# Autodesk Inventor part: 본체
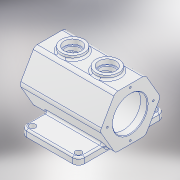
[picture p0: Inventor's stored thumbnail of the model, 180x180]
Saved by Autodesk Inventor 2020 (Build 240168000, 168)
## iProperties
Created: 2021-06
Part Number: 본체
Material: 알루미늄 6061
Document SubType Name: Modeling
Designer: MIRAE
Mass: 1495.28 g
Surface Area: 1102.36 cm^2
Volume: 553.806 cm^3
Density: 2.7 g/cm^3
Appearance: 알루미늄 - 평지
Author: MIRAE
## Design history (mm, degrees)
sketch "스케치1" dims "d0" = 105
  geometry: L1 (0, -52.5)-(-45.466, -26.25); L2 (-45.466, -26.25)-(-45.466, 26.25); L3 (-45.466, 26.25)-(0, 52.5); L4 (0, 52.5)-(45.466, 26.25); L5 (45.466, 26.25)-(45.466, -26.25); L6 (45.466, -26.25)-(0, -52.5); 3 further points
  constraints: 12 end point, 2 coincident, 1 vertical, 1 vertical alignment, 15 other
extrude "돌출1" new body sketch "스케치1" stored distance "d1" = 140; taper "d2" = 0 deg
sketch "스케치2"
  geometry: L1 (-70, 0)-(70, 0) reference; L2 (-70, 0)-(70, 0); L3 (-70, 0)-(-70, 30); L4 (-70, 45.466)-(-70, 0) reference; L5 (-70, 30)-(-58, 30); L6 (-58, 30)-(-58, 37.5); L7 (-58, 37.5)-(58, 37.5); L8 (58, 37.5)-(58, 30); L9 (58, 30)-(70, 30); L10 (70, 0)-(70, 45.466) reference; L11 (70, 30)-(70, 0); 1 further point
  constraints: 16 end point, 4 collinear, 4 perpendicular, 1 horizontal, 1 point on line
  dimensions: "d4" = 60 diameter of L5 L1; "d5" = 75 diameter of L7 L1; "d6" = 12 distance of L3.end L5.end
revolve "회전1" sketch "스케치2" stored, may be unused: angle "d7" = 90 deg
node "작업 평면1"
sketch "스케치3"
  geometry: L1 (35, -75)-(-45, -75); L2 (-55, -65)-(-55, 65); L3 (-45, 75)-(35, 75); L4 (45, 65)-(45, -65); L5 (70, -26.25)-(70, -52.5) reference; A1 r 10 centre (35, -65) between (35, -75) and (45, -65); A2 r 10 centre (-45, -65) between (-55, -65) and (-45, -75); A3 r 10 centre (-45, 65) between (-45, 75) and (-55, 65); A4 r 10 centre (35, 65) between (45, 65) and (35, 75); 4 further points
  constraints: 8 end point, 8 point on circle, 8 tangent, 6 point on line, 4 centre point, 3 equal radius, 2 parallel, 1 horizontal, 1 perpendicular
  dimensions: "d9" = 150 distance of point (-55, -75) point (-55, 75); "d10" = 25 distance between parallel lines of L4 L5; "d11" = 100 distance of point (45, -75) point (-55, -75); "d12" = 75 distance from line of point (0, 0) L1; "d13" = 10 radius of A1 (derived)
extrude "돌출2" join sketch "스케치3" distance "d14" = 12; taper "d15" = 0 deg
sketch "스케치4"
  geometry: C1 r 5.5 at (-35, 65); C2 r 5.5 at (45, 65); C3 r 5.5 at (45, -65); C4 r 5.5 at (-35, -65); A1 r 10 centre (-35, 65) between (-35, 75) and (-45, 65) reference; A2 r 10 centre (45, 65) between (55, 65) and (45, 75) reference; A3 r 10 centre (45, -65) between (45, -75) and (55, -65) reference; A4 r 10 centre (-35, -65) between (-45, -65) and (-35, -75) reference; 1 further point
  constraints: 4 centre point, 4 coincident
  dimensions: "d16" = 11 diameter of C1; "d17" = 11 diameter of C2; "d18" = 11 diameter of C3; "d19" = 11 diameter of C4
extrude "돌출3" cut sketch "스케치4" distance "d20" = 12; taper "d21" = 0 deg
node "작업 평면2"
sketch "스케치5"
  geometry: L1 (70, 26.25)-(70, -26.25) reference; C1 r 20 at (30, 0); C2 r 20 at (-30, 0); 1 further point
  constraints: 2 centre point, 2 horizontal alignment, 1 equal radius
  dimensions: "d23" = 40 distance from line of L1 C1.centre; "d24" = 60 distance of C2.centre C1.centre; "d25" = 40 diameter of C1
extrude "돌출4" join sketch "스케치5" stored distance "d26" = 12; taper "d27" = 0 deg
sketch "스케치6"
  geometry: C1 r 20 at (0, 0) reference; C2 r 20 at (60, 0) reference; 3 further points
  constraints: 2 coincident
hole "구멍1" sketch "스케치6" at (0, 0), (60, 0) diameter "d28" = 25; stored, may be unused: countersink angle "d32" = 90 deg, drill point angle "d34" = 118 deg; dims "d29" = 6, "d30" = 30, "d31" = 8, "d33" = 20
sketch "스케치7"
  geometry: L1 (0, 0)-(0, 40); L2 (0, 0)-(-28.284, 28.284); C1 r 40 at (0, 0); 2 further points
  constraints: 4 end point, 2 coincident, 1 centre point, 1 vertical
  dimensions: "d35" = 80 diameter of C1; "d36" = 45 deg angle of L1 L2; "d37" = 40 distance of L1.start L1.end; "d38" = 40 distance of point (0, 0) L2.end (= d37)
hole "구멍2" sketch "스케치7" at (-28.284, 28.284) diameter "d39" = 3.242; stored, may be unused: countersink angle "d43" = 90 deg, drill point angle "d45" = 118 deg; dims "d40" = 8, "d41" = 30, "d42" = 8, "d44" = 10
sketch "스케치8"
  geometry: C1 r 30 at (0, 0) reference; A1 r 40 centre (0, 0) between (0, 40) and (40, 0); 3 further points
  constraints: 4 point on circle, 2 horizontal alignment, 2 vertical alignment, 1 centre point, 1 coincident
  dimensions: "d49" = 80 diameter of A1
hole "구멍3" sketch "스케치8" at (0, 40), (40, 0), (0, -40), (-40, 0) diameter "d50" = 3.242; stored, may be unused: countersink angle "d54" = 90 deg, drill point angle "d56" = 118 deg; dims "d51" = 8, "d52" = 30, "d53" = 8, "d55" = 10
sketch "스케치9"
  geometry: L1 (45, 75)-(-35, 75) reference; L2 (-45, 65)-(-45, -65) reference; 2 further points
  constraints: 1 other
  dimensions: "d57" = 14 distance from line of point (5, 61) L1; "d58" = 50 distance from line of point (5, 61) L2
feature "엠보싱1" sketch "스케치9" dims "d0" = 105, "d4" = 60, "d5" = 75, "d6" = 12, "d59" = 0.5, "d60" = 0
fillet "모깎기1" dims "d61" = 5
fillet "모깎기2" dims "d62" = 8
fillet "모깎기3" dims "d63" = 3
fillet "모깎기4" dims "d64" = 3
fillet "모깎기5" dims "d65" = 3
chamfer "모따기1" distance "d66" = 1; stored, may be unused: second distance "d67" = 2, angle "d68" = 45 deg
chamfer "모따기2" distance "d69" = 1; stored, may be unused: second distance "d70" = 2, angle "d71" = 45 deg
node "솔리드1"
pattern_circular "원형 패턴1" dims angle "d47" = 360 deg
feature "A9D066F2-1C7D-4E18-AEED-F7BC21143FA4" dims "d39" = 3.242, "d40" = 8, "d41" = 30, "d42" = 8, "d43" = 90 deg, "d44" = 10, "d45" = 118 deg
other parameters: "d22" = 52.5
